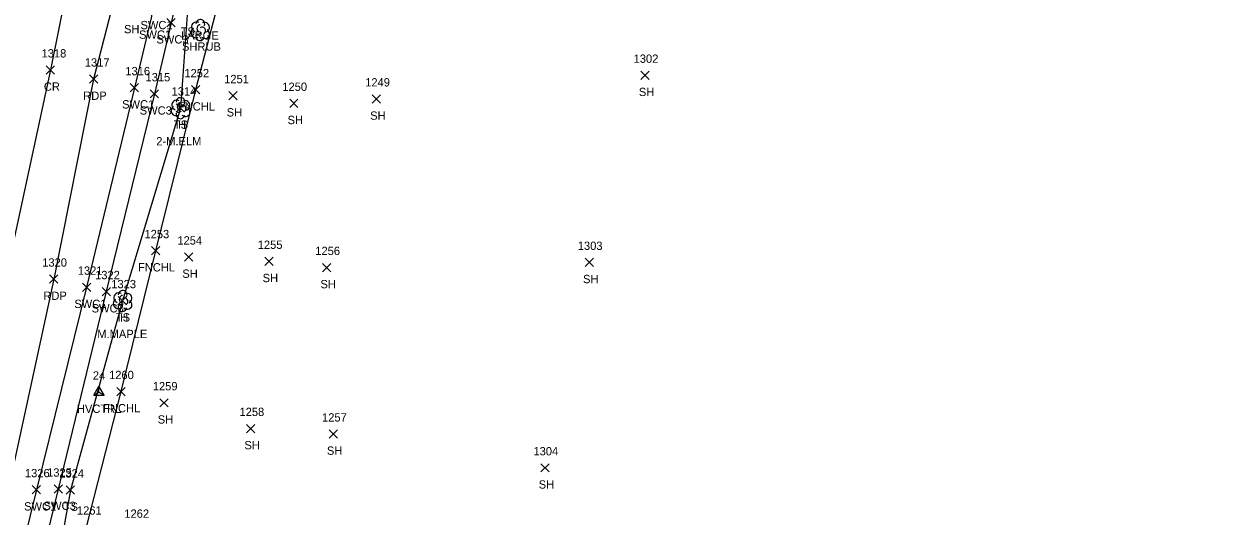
# Model space of a CAD drawing. Extents: x 1477930 to 1480780, y 774090 to 784647.
# Drawn here: x 1479397 to 1479682.6, y 774509.5 to 774628 of the extents above; entities that cross this region are included whole.
import ezdxf

# ---------------------------------------------------------------- set-up
doc = ezdxf.new("R2010")
doc.units = 0
for name, color, linetype in [('C_A', 7, 'Continuous'), ('C_I', 7, 'Continuous'), ('CPSM', 7, 'Continuous'), ('L_A', 7, 'Continuous'), ('L_C', 7, 'Continuous'), ('L_I', 7, 'Continuous'), ('L_TIC', 7, 'Continuous'), ('LELB', 7, 'Continuous'), ('LFNC', 7, 'Continuous'), ('LSH', 7, 'Continuous'), ('LTD', 7, 'Continuous'), ('P_A', 7, 'Continuous'), ('P_I', 7, 'Continuous'), ('P_TIC', 7, 'Continuous'), ('PET', 7, 'Continuous'), ('PRC', 7, 'Continuous'), ('R_A', 7, 'Continuous'), ('R_I', 7, 'Continuous'), ('R_TIC', 7, 'Continuous'), ('RSW', 7, 'Continuous')]:
    doc.layers.add(name, color=color, linetype=linetype)

msp = doc.modelspace()

# ---------------------------------------------------------------- linework, layer by layer
at = {"layer": 'CPSM'}
for p, q in [((1479413.85, 774538.67), (1479415.1, 774540.83)), ((1479416.35, 774538.67), (1479415.1, 774540.83)), ((1479415.1, 774539.39), (1479415.1, 774540.83)), ((1479413.85, 774538.67), (1479415.1, 774539.39)), ((1479413.85, 774538.67), (1479416.35, 774538.67)), ((1479415.1, 774539.39), (1479415.1, 774539.39)), ((1479415.1, 774539.39), (1479416.35, 774538.67))]:
    msp.add_line(p, q, dxfattribs=at)
at = {"layer": 'L_TIC'}
for points in [[(1479545.44, 774614.6), (1479547.44, 774616.6)], [(1479547.44, 774614.6), (1479545.44, 774616.6)], [(1479437.34, 774611.12), (1479439.34, 774613.12)], [(1479439.34, 774611.12), (1479437.34, 774613.12)], [(1479446.33, 774609.69), (1479448.33, 774611.69)], [(1479448.33, 774609.69), (1479446.33, 774611.69)], [(1479433.69, 774606.73), (1479435.69, 774608.73)], [(1479435.69, 774606.73), (1479433.69, 774608.73)], [(1479460.96, 774607.85), (1479462.96, 774609.85)], [(1479462.96, 774607.85), (1479460.96, 774609.85)], [(1479480.82, 774608.91), (1479482.82, 774610.91)], [(1479482.82, 774608.91), (1479480.82, 774610.91)], [(1479427.73, 774572.41), (1479429.73, 774574.41)], [(1479429.73, 774572.41), (1479427.73, 774574.41)], [(1479435.65, 774570.88), (1479437.65, 774572.88)], [(1479437.65, 774570.88), (1479435.65, 774572.88)], [(1479454.97, 774569.84), (1479456.97, 774571.84)], [(1479456.97, 774569.84), (1479454.97, 774571.84)], [(1479468.87, 774568.36), (1479470.87, 774570.36)], [(1479470.87, 774568.36), (1479468.87, 774570.36)], [(1479532.02, 774569.59), (1479534.02, 774571.59)], [(1479534.02, 774569.59), (1479532.02, 774571.59)], [(1479419.75, 774560.37), (1479421.75, 774562.37)], [(1479421.75, 774560.37), (1479419.75, 774562.37)], [(1479419.36, 774538.52), (1479421.36, 774540.52)], [(1479421.36, 774538.52), (1479419.36, 774540.52)], [(1479429.74, 774535.81), (1479431.74, 774537.81)], [(1479431.74, 774535.81), (1479429.74, 774537.81)], [(1479450.59, 774529.63), (1479452.59, 774531.63)], [(1479452.59, 774529.63), (1479450.59, 774531.63)], [(1479470.43, 774528.31), (1479472.43, 774530.31)], [(1479472.43, 774528.31), (1479470.43, 774530.31)], [(1479521.35, 774520.17), (1479523.35, 774522.17)], [(1479523.35, 774520.17), (1479521.35, 774522.17)], [(1479407.24, 774514.83), (1479409.24, 774516.83)], [(1479409.24, 774514.83), (1479407.24, 774516.83)]]:
    msp.add_lwpolyline(points, dxfattribs=at)
at = {"layer": 'LELB'}
msp.add_lwpolyline([(1479759.78, 774845.84), (1479743.76, 774848.1), (1479715.88, 774830.05), (1479665.38, 774803.72), (1479650.39, 774795.36), (1479602.85, 774770.48), (1479561.12, 774746.99), (1479522.68, 774719.79), (1479509.66, 774713.24), (1479482.17, 774702.33), (1479465.55, 774693.3), (1479450.04, 774680.68), (1479444.99, 774662.35), (1479439.28, 774645.05), (1479436.33, 774630.12), (1479434.69, 774607.73), (1479420.75, 774561.37), (1479408.24, 774515.83), (1479404.08, 774492.53), (1479401.08, 774483.2), (1479386.93, 774431.62)], dxfattribs=at)
at = {"layer": 'LFNC'}
msp.add_lwpolyline([(1479663.5, 774773.7), (1479660.34, 774780.67), (1479659.08, 774782.89), (1479609.82, 774754.99), (1479569.72, 774733.43), (1479526.46, 774709.45), (1479487.86, 774688.03), (1479452.66, 774667.9), (1479445.76, 774640.86), (1479438.34, 774612.12), (1479428.73, 774573.41), (1479420.36, 774539.52), (1479411.98, 774506.91), (1479408.88, 774492.5)], dxfattribs=at)
at = {"layer": 'LSH'}
msp.add_line((1479439.43, 774626.52), (1479439.43, 774626.52), dxfattribs=at)
msp.add_line((1479439.43, 774626.52), (1479439.43, 774626.52), dxfattribs=at)
msp.add_arc((1479439.48, 774627.96), 1.05, 335.5272, 180.9563, dxfattribs=at)
for centre, major_axis, ratio, start_param, end_param in [((1479438.35, 774625.81), (0.58, -1.04), 0.959034, 3.141593, 6.283185), ((1479438.64, 774627.19), (1.21, -0.51), 0.895232, 1.570796, 4.712389), ((1479439.22, 774626.98), (-0.208, -0.792), 0.645439, 3.141593, 6.283185), ((1479439.93, 774626.35), (-0.5, 0.667), 0.989748, 3.141593, 6.283185), ((1479440.43, 774625.69), (-1.09, 0.79), 0.841452, 1.570796, 4.712389), ((1479440.47, 774627.1), (-1.14, -0.48), 0.949671, 1.570796, 4.712389), ((1479439.43, 774625.02), (0.26, 1.06), 0.942809, 1.570796, 4.712389), ((1479438.97, 774625.77), (-0.625, -0.083), 0.423636, 0, 3.141593)]:
    msp.add_ellipse(centre, major_axis=major_axis, ratio=ratio, start_param=start_param, end_param=end_param, dxfattribs=at)
at = {"layer": 'LTD'}
for p, q in [((1479434.69, 774607.73), (1479434.69, 774607.73)), ((1479434.69, 774607.73), (1479434.69, 774607.73)), ((1479420.75, 774561.37), (1479420.75, 774561.37)), ((1479420.75, 774561.37), (1479420.75, 774561.37))]:
    msp.add_line(p, q, dxfattribs=at)
for centre in [(1479434.74, 774609.17), (1479420.8, 774562.81)]:
    msp.add_arc(centre, 1.05, 335.5272, 180.9563, dxfattribs=at)
for centre, major_axis, ratio, start_param, end_param in [((1479433.9, 774608.4), (1.21, -0.51), 0.895232, 1.570796, 4.712389), ((1479434.48, 774608.19), (-0.208, -0.792), 0.645439, 3.141593, 6.283185), ((1479435.73, 774608.32), (-1.14, -0.48), 0.949671, 1.570796, 4.712389), ((1479433.61, 774607.03), (0.58, -1.04), 0.959034, 3.141593, 6.283185), ((1479434.69, 774606.23), (0.26, 1.06), 0.942809, 1.570796, 4.712389), ((1479434.23, 774606.98), (-0.625, -0.083), 0.423636, 0, 3.141593), ((1479435.19, 774607.57), (-0.5, 0.667), 0.989748, 3.141593, 6.283185), ((1479435.69, 774606.9), (-1.09, 0.79), 0.841452, 1.570796, 4.712389), ((1479419.96, 774562.04), (1.21, -0.51), 0.895232, 1.570796, 4.712389), ((1479421.79, 774561.96), (-1.14, -0.48), 0.949671, 1.570796, 4.712389), ((1479419.67, 774560.66), (0.58, -1.04), 0.959034, 3.141593, 6.283185), ((1479420.29, 774560.62), (-0.625, -0.083), 0.423636, 0, 3.141593), ((1479420.54, 774561.83), (-0.208, -0.792), 0.645439, 3.141593, 6.283185), ((1479421.25, 774561.2), (-0.5, 0.667), 0.989748, 3.141593, 6.283185), ((1479421.75, 774560.54), (-1.09, 0.79), 0.841452, 1.570796, 4.712389), ((1479420.75, 774559.87), (0.26, 1.06), 0.942809, 1.570796, 4.712389)]:
    msp.add_ellipse(centre, major_axis=major_axis, ratio=ratio, start_param=start_param, end_param=end_param, dxfattribs=at)
at = {"layer": 'P_TIC'}
for points in [[(1479402.41, 774615.88), (1479404.41, 774617.88)], [(1479404.41, 774615.88), (1479402.41, 774617.88)], [(1479412.82, 774613.69), (1479414.82, 774615.69)], [(1479414.82, 774613.69), (1479412.82, 774615.69)], [(1479403.23, 774565.57), (1479405.23, 774567.57)], [(1479405.23, 774565.57), (1479403.23, 774567.57)]]:
    msp.add_lwpolyline(points, dxfattribs=at)
at = {"layer": 'PET'}
msp.add_lwpolyline([(1479713.99, 774833.47), (1479663.95, 774806), (1479649, 774797.94), (1479602.12, 774772.9), (1479559.82, 774750.06), (1479518.06, 774728.17), (1479475.57, 774706.69), (1479465.7, 774701.25), (1479434.17, 774686.11), (1479428.66, 774666.26), (1479418.77, 774633.96), (1479413.82, 774614.69), (1479404.23, 774566.57), (1479393.7, 774517.71), (1479389.34, 774499.77)], dxfattribs=at)
at = {"layer": 'PRC'}
msp.add_lwpolyline([(1479418.32, 774694.97), (1479413.6, 774667.54), (1479403.41, 774616.88), (1479393.18, 774569.31), (1479382.15, 774520.62), (1479370.95, 774473.44), (1479362, 774437.8), (1479350.26, 774392.93), (1479347.88, 774382.5), (1479334.29, 774330.6), (1479333.84, 774328.63), (1479325.02, 774295.54), (1479313.51, 774250.57), (1479296.99, 774187.82), (1479284.93, 774140.68)], dxfattribs=at)
at = {"layer": 'R_TIC'}
for points in [[(1479431.44, 774627.24), (1479433.44, 774629.24)], [(1479433.44, 774627.24), (1479431.44, 774629.24)], [(1479422.62, 774611.61), (1479424.62, 774613.61)], [(1479424.62, 774611.61), (1479422.62, 774613.61)], [(1479427.42, 774610.14), (1479429.42, 774612.14)], [(1479429.42, 774610.14), (1479427.42, 774612.14)], [(1479411.13, 774563.62), (1479413.13, 774565.62)], [(1479413.13, 774563.62), (1479411.13, 774565.62)], [(1479415.86, 774562.55), (1479417.86, 774564.55)], [(1479417.86, 774562.55), (1479415.86, 774564.55)], [(1479399.05, 774514.9), (1479401.05, 774516.9)], [(1479401.05, 774514.9), (1479399.05, 774516.9)], [(1479404.32, 774515.05), (1479406.32, 774517.05)], [(1479406.32, 774515.05), (1479404.32, 774517.05)]]:
    msp.add_lwpolyline(points, dxfattribs=at)
at = {"layer": 'RSW'}
for points in [[(1479445.73, 774683.18), (1479436.47, 774645.61), (1479432.44, 774628.24), (1479428.42, 774611.14), (1479416.86, 774563.55), (1479405.32, 774516.05), (1479399.83, 774493.77), (1479397.14, 774483.55), (1479383.7, 774432.42), (1479378.78, 774414.66), (1479376, 774403.93), (1479368.41, 774376.23), (1479354.39, 774323.87), (1479354.03, 774322.36), (1479349.26, 774304.31), (1479346.2, 774292.81), (1479333.15, 774243.56), (1479321.64, 774199.64), (1479319.46, 774190.5)], [(1479439.59, 774678.84), (1479428.06, 774631.68), (1479427.69, 774629.39), (1479423.62, 774612.61), (1479412.13, 774564.62), (1479400.05, 774515.9), (1479395.35, 774496.7), (1479392.07, 774484.83), (1479378.7, 774433.47), (1479373.97, 774416.64), (1479370.99, 774405.04), (1479364.01, 774378.3), (1479349.72, 774325.26), (1479349.32, 774323.81), (1479344.48, 774305.55), (1479341.14, 774293.48), (1479328.32, 774245.21), (1479314.62, 774191.4)]]:
    msp.add_lwpolyline(points, dxfattribs=at)

# ---------------------------------------------------------------- texts
at = {"layer": 'C_A'}
msp.add_text('HVCTRL', height=2, dxfattribs=at).set_placement((1479409.79, 774534.39))
at = {"layer": 'C_I'}
msp.add_text('24', height=2, dxfattribs=at).set_placement((1479413.63, 774542.39))
at = {"layer": 'L_A'}
for s, p in [('SH', (1479421.11, 774625.71)), ('TS', (1479434.74, 774625.12)), ('SHRUB', (1479435.06, 774621.52)), ('SH', (1479544.93, 774610.6)), ('FNCHL', (1479434.08, 774607.12)), ('SH', (1479445.81, 774605.69)), ('SH', (1479460.45, 774603.85)), ('SH', (1479480.31, 774604.91)), ('TS', (1479433.1, 774602.73)), ('H', (1479434.12, 774602.73)), ('FNCHL', (1479424.48, 774568.41)), ('SH', (1479435.14, 774566.88)), ('SH', (1479454.46, 774565.84)), ('SH', (1479468.36, 774564.36)), ('SH', (1479531.5, 774565.59)), ('TS', (1479419.16, 774556.37)), ('H', (1479420.18, 774556.37)), ('FNCHL', (1479416.1, 774534.52)), ('SH', (1479429.23, 774531.81)), ('SH', (1479450.08, 774525.63)), ('SH', (1479469.92, 774524.31)), ('SH', (1479520.84, 774516.17)), ('TS', (1479406.65, 774510.83))]:
    msp.add_text(s, height=2, dxfattribs=at).set_placement(p)
at = {"layer": 'L_C'}
for s, p in [('LARGE', (1479434.83, 774624.19)), ('2-M.ELM', (1479428.88, 774598.73)), ('M.MAPLE', (1479414.69, 774552.37))]:
    msp.add_text(s, height=2, dxfattribs=at).set_placement(p)
at = {"layer": 'L_I'}
for s, p in [('1302', (1479543.67, 774618.6)), ('1252', (1479435.64, 774615.12)), ('1251', (1479445.2, 774613.69)), ('1249', (1479479.12, 774612.91)), ('1314', (1479432.57, 774610.73)), ('1314', (1479432.57, 774610.73)), ('1250', (1479459.19, 774611.85)), ('1253', (1479426.04, 774576.41)), ('1254', (1479433.96, 774574.88)), ('1255', (1479453.28, 774573.84)), ('1303', (1479530.24, 774573.59)), ('1256', (1479467.12, 774572.36)), ('1323', (1479418.06, 774564.37)), ('1323', (1479418.06, 774564.37)), ('1260', (1479417.53, 774542.52)), ('1259', (1479428.04, 774539.81)), ('1258', (1479448.89, 774533.63)), ('1257', (1479468.74, 774532.31)), ('1304', (1479519.58, 774524.17)), ('1324', (1479405.55, 774518.83)), ('1261', (1479409.8, 774509.91)), ('1262', (1479421.2, 774509.15))]:
    msp.add_text(s, height=2, dxfattribs=at).set_placement(p)
at = {"layer": 'P_A'}
for s, p in [('CR', (1479401.85, 774611.88)), ('RDP', (1479411.31, 774609.69)), ('RDP', (1479401.72, 774561.57))]:
    msp.add_text(s, height=2, dxfattribs=at).set_placement(p)
at = {"layer": 'P_I'}
for s, p in [('1318', (1479401.29, 774619.88)), ('1317', (1479411.7, 774617.69)), ('1320', (1479401.45, 774569.57))]:
    msp.add_text(s, height=2, dxfattribs=at).set_placement(p)
at = {"layer": 'R_A'}
for s, p in [('SWC1', (1479424.73, 774624.39)), ('SWC1', (1479425.09, 774626.68)), ('SWC3', (1479428.92, 774623.24)), ('SWC1', (1479420.66, 774607.61)), ('SWC3', (1479424.89, 774606.14)), ('SWC1', (1479409.17, 774559.62)), ('SWC3', (1479413.34, 774558.55)), ('SWC1', (1479397.09, 774510.9)), ('SWC3', (1479401.79, 774511.05))]:
    msp.add_text(s, height=2, dxfattribs=at).set_placement(p)
at = {"layer": 'R_I'}
for s, p in [('1316', (1479421.44, 774615.61)), ('1315', (1479426.29, 774614.14)), ('1321', (1479410, 774567.62)), ('1322', (1479414.17, 774566.55)), ('1326', (1479397.3, 774518.9)), ('1325', (1479402.62, 774519.05))]:
    msp.add_text(s, height=2, dxfattribs=at).set_placement(p)

doc.saveas('drawing.dxf')
